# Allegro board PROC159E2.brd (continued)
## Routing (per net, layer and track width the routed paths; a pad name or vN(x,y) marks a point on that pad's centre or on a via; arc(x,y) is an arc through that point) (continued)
HSEC_EPWM1_A: length 63.2
  TOP w0.147: J15.53 v1(38.24,4.56) ; U1.D3 v1(54.58,44.83)
  L03_SIG1 w0.091: v1(54.58,44.83) 54.97,45.22 54.97,45.79 54.74,46.02 54.44,46.02 54.17,46.29 54.17,47.39 53.74,47.82 51.8,47.82 49.82,45.83 49.82,38.37 49.3,37.86 49.3,33.4 46.26,30.36 46.26,29.3 43.51,26.55 42.45,26.55 37.56,21.65 37.56,18.1 35.67,16.21 35.67,6.48 34.75,5.56 34.75,4.73 35.35,4.13 37.81,4.13 v1(38.24,4.56)
HSEC_EPWM1_B: length 50.9
  TOP w0.147: U1.D2 v1(53.78,44.83) ; J15.55 39.04,3.61 38.73,3.92 38.73,6.1 v1(38.24,6.59)
  L03_SIG1 w0.091: v1(38.24,6.59) 38.24,6.96 38.4,7.13 38.4,12.85 38.76,13.21 38.76,20.25 47.37,28.86 47.37,29.84 50.4,32.87 50.4,37 51.11,37.71 51.11,43.51 52.82,45.22 53.39,45.22 v1(53.78,44.83)
HSEC_EPWM2_A: length 52.7
  TOP w0.147: U1.C2 v1(53.78,45.63)
  L03_SIG1 w0.091: v1(36.64,5.58) 36.64,5.95 37.88,7.19 37.88,10.06 37.58,10.36 37.58,17.09 38.37,17.88 38.37,20.37 46.99,29 46.99,30 50.04,33.04 50.04,37.29 50.69,37.93 50.69,44 52.71,46.02 53.16,46.02 53.55,45.63 v1(53.78,45.63)
  BOTTOM w0.147: v1(36.64,5.58) 37.09,5.12 37.09,4.37 36.64,3.92 J15.50
HSEC_EPWM2_B: length 50.5
  TOP w0.147: U1.C1 v1(52.98,45.63)
  L03_SIG1 w0.091: v1(37.44,5.58) 37.44,6.44 38.15,7.15 38.15,13.16 38.56,13.58 38.56,20.31 47.19,28.94 47.19,29.92 50.22,32.95 50.22,37.15 50.89,37.82 50.89,43.92 52.61,45.63 v1(52.98,45.63)
  BOTTOM w0.147: J15.52 v1(37.44,5.58)
HSEC_EPWM3_A: length 43.1
  TOP w0.147: U1.E2 v1(53.78,44.03) ; U73.11 48.52,13.64 v1(49.64,14.75)
  L03_SIG1 w0.091: v1(49.64,14.75) 53.49,18.61 55.15,18.61 55.72,19.17 55.72,20.44 55.3,20.86 55.3,29.64 58.17,32.51 58.17,39.6 57.78,39.99 56.97,39.99 56.57,40.4 56.57,44.19 56.34,44.42 55.22,44.42 54.97,44.17 54.97,43.87 54.74,43.64 54.17,43.64 v1(53.78,44.03)
HSEC_EPWM3_A/HSEC_MII1_CRS(RES0: length 33
  TOP w0.147: U73.9 v1(47.22,13.18)
  BOTTOM w0.147: C318.1 31.98,11.19 U68.3 ; C318.1 31.98,8.26 33.2,7.05 36.83,7.05 38.69,5.18 38.69,4.07 38.24,3.61 J15.54 ; C318.1 34.59,9.89 35.81,8.68 42.72,8.68 v1(47.22,13.18)
HSEC_EPWM3_B: length 58.1
  TOP w0.147: U1.E3 v1(54.58,44.03)
  L03_SIG1 w0.091: v1(54.58,44.03) 54.19,44.42 54.19,45.77 53.92,46.04 53.62,46.04 53.37,46.29 53.37,46.59 53.14,46.82 52.71,46.82 50.24,44.35 50.24,38.13 49.67,37.56 49.67,33.2 46.63,30.15 46.63,29.15 37.98,20.5 37.98,18 36.04,16.06 36.04,8.4 v1(36.7,7.73)
  BOTTOM w0.147: v1(36.7,7.73) 38.35,7.73 39.04,7.04 J15.56
HSEC_EPWM4_A: length 51.2
  TOP w0.147: v1(43.84,6.59) 43.04,5.79 J15.57 ; U1.D1 v1(52.98,44.83)
  L03_SIG1 w0.091: v1(43.84,6.59) 38.95,11.48 38.95,20.18 47.56,28.79 47.56,29.77 50.59,32.8 50.59,36.88 51.33,37.62 51.33,43.18 v1(52.98,44.83)
HSEC_EPWM4_B: length 56.3
  TOP w0.147: U1.E4 v1(55.38,44.03) ; J15.59 v1(43.84,4.56)
  L03_SIG1 w0.091: v1(55.38,44.03) 55.38,44 54.97,43.58 54.97,40.47 54.68,40.18 53.69,40.18 53.34,39.83 53.34,36.61 52.97,36.25 52.97,35.3 52.48,34.81 52.48,33.03 49.41,29.96 49.41,29.09 42.85,22.53 42.85,18.97 40.36,16.48 40.36,12.7 44.42,8.64 44.77,8.64 46.42,6.99 46.42,5.59 47.02,4.99 47.22,4.99 47.47,4.74 47.47,4.38 47.22,4.13 44.27,4.13 v1(43.84,4.56)
HSEC_EPWM5_A: length 51.6
  TOP w0.147: U1.F2 v1(53.78,43.23) ; J15.61 44.64,5.79 v1(45.44,6.59)
  L03_SIG1 w0.091: v1(53.78,43.23) 53.39,43.62 52.71,43.62 51.75,42.66 51.75,36.48 51.52,36.25 51.52,35.6 51.69,35.42 51.69,33.36 48.68,30.34 48.68,29.4 39.31,20.02 39.31,12.72 v1(45.44,6.59)
HSEC_EPWM5_B: length 49.6
  TOP w0.147: U1.G2 v1(53.78,42.43) ; J15.63 v1(45.44,4.56)
  L03_SIG1 w0.091: v1(53.78,42.43) 53.52,42.17 53.48,42.17 52.42,41.1 52.42,36.94 52.77,36.59 52.77,35.42 52.27,34.92 52.27,33.11 49.23,30.08 49.23,29.17 42.44,22.37 42.44,18.94 40.12,16.62 40.12,12.69 44.35,8.46 44.69,8.46 46.23,6.92 46.23,5.35 v1(45.44,4.56)
HSEC_EPWM6_A: length 51
  TOP w0.147: U1.E1 v1(52.98,44.03)
  L03_SIG1 w0.091: v1(52.98,44.03) 52.61,44.03 51.54,42.96 51.54,37.53 50.77,36.76 50.77,34.79 51.47,34.09 51.47,33.41 47.74,29.69 47.74,28.71 39.13,20.1 39.13,12.27 v1(43.84,7.56)
  BOTTOM w0.147: v1(43.84,7.56) 43.52,7.24 43.47,7.24 43.04,6.81 J15.58
HSEC_EPWM6_B: length 54.4
  TOP w0.147: U1.F3 v1(54.58,43.23)
  L03_SIG1 w0.091: v1(54.58,43.23) 54.17,42.82 52.82,42.82 52.19,42.19 52.19,36.81 52.57,36.43 52.57,35.51 52.08,35.03 52.08,33.23 49.05,30.19 49.05,29.24 39.68,19.87 39.68,12.87 44.27,8.28 44.61,8.28 46.05,6.84 46.05,5.58 45.62,5.15 44.27,5.15 v1(43.84,5.58)
  BOTTOM w0.147: v1(43.84,5.58) 43.38,5.12 43.38,4.37 43.84,3.92 J15.60
HSEC_EPWM7_A: length 51.4
  TOP w0.147: U1.F4 v1(55.38,43.23)
  L03_SIG1 w0.091: v1(45.59,8.83) 44.5,8.83 40.63,12.69 40.63,16.43 46.47,22.27 46.47,25.89 49.6,29.02 49.6,29.85 52.69,32.94 52.69,34.71 53.19,35.21 53.19,36.18 54.17,37.16 54.17,39.62 54.41,39.87 55.26,39.87 55.77,40.38 55.77,42.84 v1(55.38,43.23)
  BOTTOM w0.147: v1(45.59,8.83) 45.59,7.76 44.64,6.81 J15.62
HSEC_EPWM7_B: length 50.7
  TOP w0.147: U1.F1 v1(52.98,43.23)
  L03_SIG1 w0.091: v1(52.98,43.23) 52.61,43.23 51.96,42.59 51.96,36.43 51.7,36.17 51.7,35.71 51.88,35.54 51.88,33.28 48.86,30.27 48.86,29.32 39.49,19.95 39.49,12.8 45.18,7.11 45.52,7.11 45.87,6.77 45.87,6 v1(45.44,5.58)
  BOTTOM w0.147: v1(45.44,5.58) 44.98,5.12 44.98,4.37 45.44,3.92 J15.64
HSEC_EPWM11_A: length 67.9
  TOP w0.147: v1(47.62,45.45) 48.13,44.95 49.04,44.95 R190.2
  L03_SIG1 w0.091: v1(47.62,45.45) 48,45.07 48.5,45.07 49.59,43.98 49.59,38.54 49.12,38.06 49.12,34.5 37.08,22.46 v1(37.08,20.43)
  BOTTOM w0.147: v1(37.08,20.43) 48.55,20.43 51.54,17.45 53.42,17.45 54.36,16.51 54.36,15.84 55.68,14.52 55.68,12.42 56.35,11.75 56.35,8.73 54.24,6.62 J15.86
HSEC_EPWM13_A: length 108.5
  TOP w0.147: v1(102.44,5.58) 102.44,4.87 101.64,4.07 J15.153
  L08_SIG2 w0.091: v1(102.44,5.58) 101.67,5.58 101.18,6.07 99.06,6.07 98.01,7.11 97.42,7.11 97.03,7.51 97.03,8.69 90.94,14.77 87.73,14.77 82.67,19.83 82.67,27.73 79,31.4 79,38.58 77.39,40.19 77.39,45.49 75.06,47.82 75.06,48.91 73.62,50.35 70.8,50.35 70.48,50.67 70.48,51.2 69.55,52.13 67.79,52.13 67.03,52.89 66.03,52.89 64.87,54.06 58.3,54.06 55.76,51.51 45.03,51.51 44.23,50.72 44.23,48.09 45.11,47.22 48.66,47.22 49.4,46.48 49.4,45.24 v1(48.51,44.35)
  BOTTOM w0.147: R192.2 v1(48.51,44.35)
HSEC_EPWM13_B: length 112
  L08_SIG2 w0.091: v1(48.51,43.21) 48.08,43.64 48.08,44.53 48.33,44.78 48.66,44.78 49.12,45.24 49.12,46.32 48.56,46.88 45.07,46.88 43.97,47.98 43.97,50.78 44.88,51.69 55.56,51.69 58.12,54.25 64.95,54.25 66.11,53.09 67.11,53.09 67.87,52.33 69.7,52.33 70.75,51.27 70.75,50.79 70.94,50.6 73.78,50.6 75.17,49.22 76.83,49.22 77.66,48.38 77.66,40.31 79.24,38.73 79.24,31.5 82.91,27.83 82.91,20.02 87.87,15.06 92.18,15.06 98.36,8.88 98.36,7.71 98.97,7.1 101.07,7.1 101.58,6.59 v1(102.44,6.59)
  BOTTOM w0.147: J15.154 101.64,4.06 101.91,4.34 101.91,6.07 v1(102.44,6.59) ; R196.2 v1(48.51,43.21)
HSEC_EPWM21_A: length 45.1
  TOP w0.147: J15.89 55.84,5.87 v1(55.09,6.61) ; v1(74.47,35.69) 74.21,35.95 R209.2
  L03_SIG1 w0.091: v1(55.09,6.61) 55.52,6.61 63.52,14.61 65.34,14.61 69.32,18.59 69.32,22.46 70.98,24.13 70.98,26.99 73.72,29.74 73.72,30.96 75.94,33.18 75.94,34.22 v1(74.47,35.69)
HSEC_EPWM21_B: length 47.1
  TOP w0.147: R207.2 74.21,38.51 74.47,38.26 v1(74.47,37.75)
  L03_SIG1 w0.091: v1(56.6,6.61) 56.6,7.14 63.74,14.28 65.49,14.28 69.61,18.4 69.61,22.38 71.22,23.99 71.22,26.78 74.08,29.64 74.08,30.47 76.29,32.67 76.29,35.93 v1(74.47,37.75)
  BOTTOM w0.147: v1(56.6,6.61) 55.84,5.85 J15.90
HSEC_EQEP0_A: length 59
  TOP w0.147: U1.B14 v1(64.18,46.43)
  L08_SIG2 w0.091: v1(64.18,46.43) 64.59,46.84 65.14,46.84 65.37,47.07 65.37,47.37 65.62,47.62 66.23,47.62 66.94,46.91 66.94,45.43 71.39,40.97 71.39,39.4 72.03,38.75 72.03,34.76 70.41,33.14 70.41,30.21 71.59,29.03 71.59,27.48 71.17,27.06 71.17,23.86 69.8,22.49 69.8,18.7 66.92,15.82 65.18,15.82 60.04,10.67 60.04,8.41 60.83,7.62 61.17,7.62 v1(61.43,7.35)
  BOTTOM w0.147: J15.102 60.64,6.56 v1(61.43,7.35)
HSEC_EQEP0_B: length 67.7
  TOP w0.147: U1.A14 v1(64.18,47.23)
  L08_SIG2 w0.091: v1(64.18,47.23) 65.01,48.06 67.48,48.06 68.36,47.19 68.36,44.99 69.71,43.63 70.45,43.63 71.06,43.02 71.06,42.06 72.7,40.41 72.7,34.66 72.22,34.17 72.22,27.03 73.67,25.57 73.67,23.68 72.49,22.5 72.49,18.69 71.67,17.87 69.51,17.87 64.94,13.3 64.94,10.54 64.33,9.93 62.85,9.93 61.51,11.26 61.01,11.26 60.22,10.47 60.22,8.49 60.81,7.9 61.49,7.9 61.87,7.52 61.87,6.41 61.62,6.16 60.11,6.16 v1(59.81,6.46)
  BOTTOM w0.147: v1(59.81,6.46) 60.29,5.98 60.29,4.37 59.84,3.91 J15.100
HSEC_EQEP0_INDEX: length 76.8
  TOP w0.147: U1.D11 v1(61.78,44.83)
  L08_SIG2 w0.091: v1(61.78,44.83) 62.17,45.22 62.17,52.26 62.76,52.84 63.48,52.84 63.86,52.47 63.86,51.78 65.44,50.2 66.74,50.2 67.46,49.48 68.19,49.48 69.87,47.8 70.51,47.8 70.89,47.42 70.89,46.17 73.38,43.69 74.14,43.69 74.49,43.34 74.49,38.83 75.17,38.15 75.17,34.83 76.16,33.84 76.16,17.77 75.13,16.75 69.97,16.75 67.34,14.12 67.34,13.27 66.56,12.49 66.56,10.15 63.99,7.57 v1(63.03,7.57)
  BOTTOM w0.147: J15.106 62.24,6.78 v1(63.03,7.57)
HSEC_EQEP0_STROBE: length 69.7
  TOP w0.147: U1.C12 v1(62.58,45.63)
  L08_SIG2 w0.091: v1(62.58,45.63) 62.99,46.04 62.99,46.59 63.37,46.97 63.37,47.85 64.82,49.3 66.39,49.3 67.09,48.61 67.65,48.61 68.85,47.41 68.85,45.19 69.92,44.12 70.99,44.12 73.43,41.68 73.43,34.62 72.88,34.06 72.88,31.42 73.43,30.87 73.43,29.58 72.96,29.11 72.96,26.97 74.16,25.78 74.16,23.48 72.98,22.3 72.98,18.49 71.99,17.5 69.66,17.5 65.31,13.15 65.31,10.39 64.41,9.49 60.96,9.49 60.6,9.13 60.6,8.62 60.96,8.27 61.64,8.27 62.23,7.68 62.23,5.92 61.81,5.5 v1(61.44,5.5)
  BOTTOM w0.147: J15.104 61.44,3.92 60.98,4.37 60.98,5.04 v1(61.44,5.5)
HSEC_EQEP2_A: length 137
  L08_SIG2 w0.091: v1(24.82,18.59) 24.23,18.59 24.04,18.41 18.48,18.41 13.71,23.18 13.71,26.78 12.81,27.68 12.81,31.58 13.49,32.25 14.05,32.25 17.03,35.23 17.03,36.69 14.76,38.96 14.76,53.8 19.09,58.13 19.09,60.71 26.15,67.77 28,67.77 29.01,68.78 v1(46.04,68.78)
  BOTTOM w0.147: U26.6 46.22,68.96 v1(46.04,68.78) ; v1(24.82,18.59) 26.14,19.92 35.77,19.92 37.09,21.24 49.31,21.24 52.58,17.98 55.17,17.98 57.14,16 57.14,4.42 56.83,4.1 56.82,4.1 56.64,3.93 J15.92
HSEC_EQEP2_B: length 148.8
  TOP w0.147: J15.93 57.44,5.79 v1(58.24,6.59)
  L08_SIG2 w0.091: v1(23.87,17.51) 17.46,17.51 12.96,22.01 12.96,22.81 11.79,23.98 11.08,23.98 10.09,24.97 10.09,31.65 11.24,32.8 13.83,32.8 15.54,34.52 15.54,36.88 13.9,38.53 13.9,58.78 26.2,71.08 30.54,71.08 31.32,70.29 45.6,70.29 v1(46.03,70.73)
  BOTTOM w0.147: v1(46.03,70.73) 46.05,70.73 46.23,70.91 U26.3 ; v1(58.24,6.59) 58.24,7.15 59.77,8.68 59.77,14.55 56.05,18.27 52.7,18.27 49.43,21.54 36.97,21.54 35.64,20.21 25.81,20.21 24.65,19.05 24.63,19.05 23.87,18.29 v1(23.87,17.51)
HSEC_EQEP2_INDEX: length 71.5
  TOP w0.147: U1.A12 v1(62.58,47.23)
  L08_SIG2 w0.091: v1(62.58,47.23) 62.58,48.05 64.32,49.79 66.57,49.79 67.3,49.05 67.89,49.05 69.33,47.61 69.33,46.42 73.92,41.83 73.92,34.48 74.25,34.15 74.39,34.15 74.89,33.66 74.89,31.49 74.56,31.16 74.56,28.83 75.54,27.85 75.54,17.84 74.83,17.14 69.81,17.14 65.82,13.15 65.82,11.26 66.38,10.7 66.38,10.22 65.03,8.88 v1(61.21,8.88)
  BOTTOM w0.147: v1(61.21,8.88) 60.38,8.88 58.69,7.19 58.69,6.4 57.44,5.15 J15.94
HSEC_EQEP2_STROBE: length 77.2
  TOP w0.147: J15.95 v1(58.24,4.56) ; U1.B12 v1(62.58,46.43)
  L08_SIG2 w0.091: v1(58.24,4.56) 58.67,4.99 60.02,4.99 60.27,4.74 60.27,4.61 61.11,3.77 62.85,3.77 63.47,4.38 63.47,6.67 63.17,6.96 62.78,6.96 62.42,7.32 62.42,7.74 61.71,8.45 61.03,8.45 60.78,8.7 60.78,9.05 61.03,9.3 64.48,9.3 65.49,10.31 65.49,13.07 69.74,17.32 74.67,17.32 75.3,17.94 75.3,27.75 73.91,29.14 73.91,33.88 73.68,34.11 73.68,41.75 71.09,44.34 70.01,44.34 69.07,45.28 69.07,47.53 67.78,48.83 67.19,48.83 66.47,49.54 64.61,49.54 63.08,48.01 63.08,47.16 62.58,46.66 v1(62.58,46.43)
HSEC_EXT_REFCLK0: length 45.5
  TOP w0.147: U1.P2 v1(53.78,36.03)
  L03_SIG1 w0.091: v1(53.78,36.03) 53.39,35.64 53.39,35.08 52.91,34.6 52.91,32.85 49.78,29.73 49.78,28.94 47.94,27.1 47.94,22.72 41.38,16.16 41.38,12.72 44.43,9.67 46.2,9.67 47.26,8.62 49.23,8.62 v1(50.24,7.61)
  BOTTOM w0.147: J15.74 49.44,6.81 v1(50.24,7.61)
HSEC_GPIO: length 94.1
  TOP w0.147: v1(52.75,67.83) 52.25,68.33 45.59,68.33 44.37,67.11 44.37,61.86 43.83,61.31 43.83,60.4 46.44,57.78 v1(46.44,56.66)
  BOTTOM w0.147: v1(46.44,56.66) 46.44,55.92 42.39,51.87 42.39,47.14 47.05,42.48 47.05,40.79 45.35,39.09 45.35,36.74 43.95,35.35 43.95,31.83 49.1,26.69 49.1,24.3 51.47,21.92 57.47,21.92 58.58,20.81 58.58,17.73 61.72,14.6 61.72,8.74 60.02,7.05 59.75,7.05 58.99,6.28 58.99,6.28 57.78,5.08 57.78,4.37 58.24,3.92 J15.96 ; U60.17 52.9,68.24 52.75,68.09 v1(52.75,67.83)
HSEC_I2C1_SCL: length 97.8
  TOP w0.147: U1.D7 v1(57.78,44.83) ; J15.87 v1(55.04,4.56) ; R152.2 v1(57.84,49.14)
  L08_SIG2 w0.091: v1(55.04,4.56) 56.2,3.4 63,3.4 63.83,4.23 63.83,6.64 66.79,9.6 67.11,9.92 67.11,12.21 69.29,14.39 74.72,14.39 81.14,20.81 81.14,28.6 78.45,31.28 78.45,38.35 76.84,39.97 76.84,43.97 74.47,46.33 74.47,48.69 73.33,49.82 70.06,49.82 69.26,50.62 69.26,51.24 68.75,51.75 67.62,51.75 66.86,52.51 65.87,52.51 64.79,53.58 61.72,53.58 60.45,52.32 60.11,52.32 59.53,51.74 59.53,51.4 57.84,49.71 v1(57.84,49.14) 59.17,47.8 59.17,46.77 58.97,46.57 58.97,45.47 58.74,45.24 58.19,45.24 v1(57.78,44.83)
HSEC_I2C1_SDA: length 103
  TOP w0.147: v1(55.03,5.62) 54.71,5.3 54.71,5.29 54.24,4.82 J15.85 ; R153.2 v1(56.7,49.14) ; U1.C8 v1(58.58,45.63)
  L08_SIG2 w0.091: v1(55.03,5.62) 54.61,5.21 54.61,4.38 55.78,3.22 63.08,3.22 64.01,4.16 64.01,6.45 67.3,9.74 67.3,12.14 69.37,14.21 74.88,14.21 81.38,20.71 81.38,28.67 78.76,31.3 78.76,38.44 77.11,40.08 77.11,45.38 74.83,47.66 74.83,48.74 73.46,50.1 70.18,50.1 69.51,50.76 69.51,51.4 68.97,51.94 67.7,51.94 66.94,52.7 65.95,52.7 64.87,53.79 61.5,53.79 60.36,52.64 59.98,52.64 59.52,52.18 58.56,52.18 56.7,50.32 v1(56.7,49.14) 57.18,48.65 57.8,48.65 58.97,47.48 58.97,47.07 58.74,46.84 58.44,46.84 58.19,46.59 58.19,46.02 v1(58.58,45.63)
HSEC_MCAN5_RX: length 48.3
  L03_SIG1 w0.091: v1(47.38,24.5) 46.9,24.02 46.9,22.37 40.9,16.37 40.9,12.68 44.28,9.31 45.97,9.31 47.03,8.25 48.6,8.25 49.81,7.04 49.81,6.41 50.65,5.58 v1(51.84,5.58)
  BOTTOM w0.147: v1(51.84,5.58) 51.38,5.12 51.38,4.37 51.84,3.92 J15.80 ; v1(47.38,24.5) 45.86,26.01 43.96,26.01 38.15,31.82 U33.11
HSEC_MCAN5_TX: length 50
  L03_SIG1 w0.091: v1(53.44,7.61) 53.01,7.18 50.06,7.18 48.81,8.43 47.11,8.43 46.05,9.49 44.35,9.49 41.16,12.68 41.16,16.29 47.33,22.46 v1(47.33,23.63)
  BOTTOM w0.147: U33.14 35.34,29.87 36.3,30.83 38.64,30.83 43.8,25.67 45.28,25.67 v1(47.33,23.63) ; J15.82 52.64,6.81 v1(53.44,7.61)
HSEC_MII0_COL: length 122.7
  TOP w0.147: v1(72.9,66.32) 73.3,65.92 73.3,64.07 73.98,63.39 U87.24
  L03_SIG1 w0.091: v1(72.9,66.32) 73.19,66.02 75.49,66.02 76.96,67.49 76.96,67.78 77.37,68.19 78.64,68.19 84.17,62.66 84.17,56.59 86.42,54.34 86.42,49.64 86.81,49.25 86.81,47.35 86.5,47.04 86.5,44.42 83.8,41.72 83.8,32.88 84.78,31.9 84.78,22.98 89.31,18.45 89.31,17.23 90.24,16.3 90.65,16.3 90.96,15.99 90.96,15.38 91.61,14.73 91.61,13.7 92.27,13.05 92.27,12.33 91.65,11.71 91.65,8.88 92.13,8.39 92.62,8.39 93.1,8.86 v1(93.51,8.86)
  BOTTOM w0.147: v1(93.51,8.86) 93.89,9.25 93.89,10.64 93.07,11.46 90.43,11.46 89.62,12.27 89.62,12.74 88.76,13.6 69.83,13.6 69.23,12.99 69.23,11.79 64.64,7.2 64.64,6.59 63.62,5.57 63.62,4.26 63.84,4.04 J15.110
HSEC_MII0_CRS: length 87.8
  TOP w0.147: v1(92.46,8.87) 90,8.87 88.84,7.71 J15.121 ; U87.22 74.17,65 v1(74.17,66.7)
  L03_SIG1 w0.091: v1(92.46,8.87) 92.08,8.87 91.89,9.06 91.89,11.55 92.54,12.2 92.54,13.16 91.93,13.78 91.93,14.81 91.24,15.5 91.24,16.19 90.95,16.48 90.95,16.96 90.65,17.26 90.19,17.26 89.69,17.76 89.69,18.58 85.05,23.22 85.05,32.02 84.07,33 84.07,41.6 86.78,44.31 86.78,45.98 87.85,47.05 87.85,48.64 86.69,49.8 86.69,54.46 84.44,56.71 84.44,62.78 83.52,63.69 79.08,68.13 79.08,68.79 78.76,69.11 77.37,69.11 76.55,68.29 76.55,67.94 75.82,67.21 74.68,67.21 v1(74.17,66.7)
HSEC_MII0_RXCLK: length 98.1
  TOP w0.147: J15.123 89.64,3.85 90.15,4.36 90.15,7.16 v1(89.57,7.73) ; U87.28 v1(73.94,61.39)
  L03_SIG1 w0.091: v1(73.94,61.39) 73.48,61.85 73.48,62.56 75.2,64.28 77.86,64.28 78.69,65.11 79.32,65.11 82,62.43 82,61.39 81.76,61.16 81.76,51.26 80.68,50.17 80.68,44.55 81.09,44.13 81.09,42.48 79.46,40.85 79.46,28.97 79.82,28.61 79.82,27.82 80.29,27.35 80.29,26.76 80.42,26.62 80.78,26.62 80.91,26.49 80.91,26.3 80.78,26.17 80.42,26.17 80.29,26.03 80.29,25.84 80.42,25.71 80.78,25.71 80.91,25.57 80.91,25.39 80.78,25.25 80.42,25.25 80.29,25.12 80.29,24.93 80.42,24.79 80.78,24.79 80.91,24.66 80.91,24.47 80.78,24.34 80.42,24.34 80.29,24.2 80.29,24.01 80.42,23.88 80.78,23.88 80.91,23.75 80.91,23.56 80.78,23.42 80.42,23.42 80.29,23.29 80.29,23.1 80.42,22.97 80.78,22.97 80.91,22.83 80.91,22.64 80.78,22.51 80.42,22.51 80.29,22.37 80.29,22.19 80.42,22.05 80.78,22.05 80.91,21.92 80.91,21.73 80.78,21.59 80.42,21.59 80.29,21.46 80.29,21.27 80.42,21.14 80.78,21.14 80.91,21 80.91,20.81 80.78,20.68 80.42,20.68 80.29,20.55 80.29,19.55 78.25,17.52 78.25,16.45 78.64,16.06 79.39,16.06 79.52,16.2 79.52,16.6 79.65,16.74 79.84,16.74 79.98,16.6 79.98,16.2 80.11,16.06 80.3,16.06 80.43,16.2 80.43,16.6 80.57,16.74 80.76,16.74 80.89,16.6 80.89,16.2 81.03,16.06 81.22,16.06 81.35,16.2 81.35,16.6 81.48,16.74 81.67,16.74 81.81,16.6 81.81,16.2 81.94,16.06 82.13,16.06 82.26,16.2 82.26,16.6 82.4,16.74 82.59,16.74 82.72,16.6 82.72,16.2 82.85,16.06 83.04,16.06 83.18,16.2 83.18,16.6 83.31,16.74 83.5,16.74 83.63,16.6 83.63,16.2 83.77,16.06 83.96,16.06 84.09,16.2 84.09,16.6 84.23,16.74 84.42,16.74 84.55,16.6 84.55,16.2 84.68,16.06 86.66,16.06 89.27,13.46 89.27,8.04 v1(89.57,7.73)
HSEC_MII0_RXD0: length 98.3
  TOP w0.147: v1(72.18,55.11) 72.93,54.36 76.63,54.36 77.22,54.95 U87.42 ; J15.125 90.44,4.1 90.73,4.4 90.73,7.1 v1(91.24,7.61)
  L03_SIG1 w0.091: v1(91.24,7.61) 91.24,11.69 91.99,12.44 91.99,12.9 91.34,13.55 91.34,14.58 90.68,15.23 90.41,15.23 88.74,16.89 88.74,18.46 84.5,22.7 84.5,31.75 83.52,32.73 83.52,41.84 85.09,43.4 85.09,48.92 84.65,49.36 84.65,53.58 83.89,54.34 83.89,62.48 79.17,67.2 77.15,67.2 75.65,65.69 72.69,65.69 70.55,63.55 70.55,58.42 71.01,57.97 71.4,57.97 71.72,57.64 71.72,56.64 72.18,56.17 v1(72.18,55.11)
HSEC_MII0_RXD1: length 98.2
  TOP w0.147: U87.40 76.22,55.26 76.07,55.11 74.99,55.11 74.79,55.32 v1(74.33,55.32)
  L03_SIG1 w0.091: v1(74.33,55.32) 74.61,55.59 74.61,59 74.2,59.41 73.74,59.41 73.5,59.65 73.5,61.45 73.21,61.73 73.21,62.75 75.02,64.56 77.75,64.56 78.57,65.38 79.44,65.38 82.33,62.48 82.33,61.3 82.04,61 82.04,51.15 80.95,50.06 80.95,44.66 81.37,44.25 81.37,42.3 79.73,40.67 79.73,29.87 81.42,28.19 81.42,24.54 81.55,24.41 81.95,24.41 82.08,24.27 82.08,24.08 81.95,23.95 81.55,23.95 81.42,23.81 81.42,23.63 81.55,23.49 81.95,23.49 82.08,23.36 82.08,23.17 81.95,23.03 81.55,23.03 81.42,22.9 81.42,22.71 81.55,22.58 81.95,22.58 82.08,22.44 82.08,22.25 81.95,22.12 81.55,22.12 81.42,21.99 81.42,21.8 81.55,21.66 81.95,21.66 82.08,21.53 82.08,21.34 81.95,21.21 81.55,21.21 81.42,21.07 81.42,20.88 81.55,20.75 81.95,20.75 82.08,20.61 82.08,20.43 81.95,20.29 81.55,20.29 81.42,20.16 81.42,19.97 81.55,19.83 81.95,19.83 82.08,19.7 82.08,19.51 81.95,19.38 81.55,19.38 81.42,19.24 81.42,19.05 81.55,18.92 81.95,18.92 82.08,18.79 82.08,18.6 81.95,18.46 81.55,18.46 81.42,18.33 81.42,17.79 81.97,17.24 85.87,17.24 89.54,13.57 89.54,9.65 90.01,9.19 90.01,5.94 v1(89.64,5.58)
  BOTTOM w0.147: J15.126 90.44,4.78 v1(89.64,5.58)
HSEC_MII0_RXD2: length 98.6
  TOP w0.147: U87.37 v1(73.94,56.89) ; J15.127 91.24,3.9 91.71,4.37 91.71,5.1 v1(91.24,5.58)
  L03_SIG1 w0.091: v1(73.94,56.89) 72.43,58.4 71.86,58.4 71.37,58.89 70.99,58.89 70.83,59.06 70.83,63.44 72.81,65.42 77.45,65.42 78.23,66.2 79.78,66.2 83.32,62.66 83.32,61.13 82.86,60.66 82.86,50.24 83.76,49.34 83.76,47.07 82.53,45.84 82.53,36.36 82.66,36.23 82.98,36.23 83.11,36.09 83.11,35.9 82.98,35.77 82.66,35.77 82.53,35.64 82.53,35.45 82.66,35.31 82.98,35.31 83.11,35.18 83.11,34.99 82.98,34.86 82.66,34.86 82.53,34.72 82.53,34.53 82.66,34.4 82.98,34.4 83.11,34.26 83.11,34.07 82.98,33.94 82.66,33.94 82.53,33.81 82.53,33.62 82.66,33.48 82.98,33.48 83.11,33.35 83.11,33.16 82.98,33.03 82.66,33.03 82.53,32.89 82.53,32.7 82.66,32.57 82.98,32.57 83.11,32.44 83.11,32.25 82.98,32.11 82.66,32.11 82.53,31.98 82.53,31.79 82.66,31.65 82.98,31.65 83.11,31.52 83.11,31.33 82.98,31.2 82.66,31.2 82.53,31.06 82.53,30.87 82.66,30.74 82.98,30.74 83.11,30.61 83.11,30.42 82.98,30.28 82.66,30.28 82.53,30.15 82.53,29.96 82.66,29.83 82.98,29.83 83.11,29.69 83.11,29.5 82.98,29.37 82.66,29.37 82.53,29.23 82.53,28.82 83.33,28.01 83.33,19.06 83.88,18.51 85.93,18.51 89.5,14.94 90.58,14.94 91.03,14.49 91.03,13.38 91.14,13.28 91.14,12.33 90.8,12 90.8,6.01 v1(91.24,5.58)
HSEC_MII0_RXD3: length 98.4
  TOP w0.147: U87.35 v1(73.94,57.89)
  L03_SIG1 w0.091: v1(73.94,57.89) 73.41,57.89 72.86,58.44 72.86,58.87 72.34,59.39 71.99,59.39 71.68,59.7 71.68,63.11 71.96,63.39 72.98,63.39 74.73,65.15 77.56,65.15 78.34,65.93 79.66,65.93 82.97,62.62 82.97,61.16 82.59,60.78 82.59,49.88 82.86,49.6 82.86,46.57 82.17,45.88 82.17,41.1 82.04,40.97 81.29,40.97 81.16,40.83 81.16,40.65 81.29,40.51 82.04,40.51 82.17,40.38 82.17,39.55 81.54,38.91 81.54,38.59 81.67,38.46 81.99,38.46 82.13,38.32 82.13,38.13 81.99,38 81.67,38 81.54,37.87 81.54,37.68 81.67,37.54 81.99,37.54 82.13,37.41 82.13,37.22 81.99,37.09 81.67,37.09 81.54,36.95 81.54,36.76 81.67,36.63 81.99,36.63 82.13,36.49 82.13,36.3 81.99,36.17 81.67,36.17 81.54,36.04 81.54,35.85 81.67,35.71 81.99,35.71 82.13,35.58 82.13,35.39 81.99,35.26 81.67,35.26 81.54,35.12 81.54,34.93 81.67,34.8 81.99,34.8 82.13,34.67 82.13,34.48 81.99,34.34 81.67,34.34 81.54,34.21 81.54,34.02 81.67,33.88 81.99,33.88 82.13,33.75 82.13,33.56 81.99,33.43 81.67,33.43 81.54,33.29 81.54,33.1 81.67,32.97 81.99,32.97 82.13,32.84 82.13,32.65 81.99,32.51 81.67,32.51 81.54,32.38 81.54,32.19 81.67,32.06 81.99,32.06 82.13,31.92 82.13,31.73 81.99,31.6 81.67,31.6 81.54,31.46 81.54,31.28 81.67,31.14 81.99,31.14 82.13,31.01 82.13,30.82 81.99,30.68 81.67,30.68 81.54,30.55 81.54,30.36 81.67,30.23 81.99,30.23 82.13,30.09 82.13,29.9 81.99,29.77 81.67,29.77 81.54,29.64 81.54,29.25 82.98,27.81 82.98,18.63 83.46,18.15 85.81,18.15 90.86,13.1 90.86,12.44 90.55,12.13 90.55,5.25 v1(91.24,4.56)
  BOTTOM w0.147: J15.128 v1(91.24,4.56)
HSEC_MII0_RXDV: length 98.3
  TOP w0.147: U87.33 v1(73.94,58.89)
  L03_SIG1 w0.091: v1(89.64,4.56) 90.26,5.19 90.26,9.36 89.81,9.81 89.81,13.71 85.84,17.69 83.14,17.69 82.59,18.24 82.59,24.71 82.45,24.85 81.91,24.85 81.78,24.98 81.78,25.17 81.91,25.3 82.45,25.3 82.59,25.44 82.59,25.63 82.45,25.76 81.91,25.76 81.78,25.89 81.78,26.08 81.91,26.22 82.45,26.22 82.59,26.35 82.59,27.76 80.76,29.59 80.76,32.25 80.01,33 80.01,34.27 80.14,34.41 81.05,34.41 81.19,34.54 81.19,34.73 81.05,34.86 80.14,34.86 80.01,35 80.01,35.19 80.14,35.32 81.05,35.32 81.19,35.46 81.19,35.64 81.05,35.78 80.14,35.78 80.01,35.91 80.01,36.87 80.14,37.01 81.07,37.01 81.21,37.14 81.21,37.33 81.07,37.46 80.14,37.46 80.01,37.6 80.01,37.79 80.14,37.92 81.07,37.92 81.21,38.05 81.21,38.24 81.07,38.38 80.14,38.38 80.01,38.51 80.01,38.7 80.14,38.83 81.07,38.83 81.21,38.97 81.21,39.16 81.07,39.29 80.14,39.29 80.01,39.43 80.01,40.36 81.64,41.99 81.64,46.54 81.98,46.88 81.98,50.67 82.31,51 82.31,60.89 82.64,61.22 82.64,62.57 79.55,65.66 78.46,65.66 77.67,64.87 74.84,64.87 72.87,62.9 72.87,60.38 72.59,60.1 72.59,59.66 73.36,58.89 v1(73.94,58.89)
  BOTTOM w0.147: J15.124 v1(89.64,4.56)
HSEC_MII0_RXER: length 98.2
  TOP w0.147: U87.31 v1(73.94,59.89)
  L03_SIG1 w0.091: v1(73.94,59.89) 73.94,60.5 74.61,61.18 74.61,62.28 75.45,63.12 77.69,63.12 78.5,63.93 79.72,63.93 81.35,62.31 81.35,61.51 81.22,61.38 81.22,51.49 80.13,50.4 80.13,44.33 78.32,42.52 78.32,24.71 78.73,24.31 78.73,23.87 78.6,23.74 77.8,23.74 77.67,23.6 77.67,23.41 77.8,23.28 78.6,23.28 78.73,23.15 78.73,22.96 78.6,22.82 77.8,22.82 77.67,22.69 77.67,22.5 77.8,22.36 78.6,22.36 78.73,22.23 78.73,19.25 77.41,17.92 77.41,15.87 78.04,15.24 v1(83.12,15.24)
  BOTTOM w0.147: v1(83.12,15.24) 81.77,13.89 69.71,13.89 69.54,13.72 68.93,13.11 68.93,11.91 64.09,7.06 64.09,6.63 62.58,5.12 62.58,4.37 63.04,3.92 J15.108
HSEC_MII0_RXLINK: length 98.1
  TOP w0.147: U87.26 v1(73.94,62.39)
  L03_SIG1 w0.091: v1(73.94,62.39) 74.27,62.39 75.28,63.4 77.58,63.4 77.98,63.8 77.98,64.02 78.8,64.83 79.21,64.83 81.62,62.42 81.62,61.4 81.49,61.27 81.49,51.37 80.4,50.29 80.4,44.21 78.6,42.41 78.6,41.72 78.71,41.62 79.08,41.62 79.19,41.51 79.19,41.36 79.08,41.25 78.71,41.25 78.6,41.14 78.6,40.99 78.71,40.88 79.08,40.88 79.19,40.78 79.19,40.63 79.08,40.52 78.71,40.52 78.6,40.41 78.6,40.26 78.71,40.15 79.08,40.15 79.19,40.05 79.19,39.89 79.08,39.79 78.71,39.79 78.6,39.68 78.6,39.53 78.71,39.42 79.08,39.42 79.19,39.31 79.19,39.16 79.08,39.06 78.71,39.06 78.6,38.95 78.6,38.8 78.71,38.69 79.08,38.69 79.19,38.58 79.19,38.43 79.08,38.32 78.71,38.32 78.6,38.22 78.6,38.07 78.71,37.96 79.08,37.96 79.19,37.85 79.19,37.7 79.08,37.59 78.71,37.59 78.6,37.49 78.6,37.33 78.71,37.23 79.08,37.23 79.19,37.12 79.19,36.97 79.08,36.86 78.71,36.86 78.6,36.75 78.6,36.6 78.71,36.5 79.08,36.5 79.19,36.39 79.19,36.24 79.08,36.13 78.71,36.13 78.6,36.02 78.6,35.87 78.71,35.76 79.08,35.76 79.19,35.66 79.19,35.51 79.08,35.4 78.71,35.4 78.6,35.29 78.6,35.14 78.71,35.03 79.08,35.03 79.19,34.93 79.19,34.77 79.08,34.67 78.71,34.67 78.6,34.56 78.6,34.41 78.71,34.3 79.08,34.3 79.19,34.19 79.19,34.04 79.08,33.94 78.71,33.94 78.6,33.83 78.6,33.68 78.71,33.57 79.08,33.57 79.19,33.46 79.19,33.31 79.08,33.2 78.71,33.2 78.6,33.1 78.6,32.95 78.71,32.84 79.08,32.84 79.19,32.73 79.19,32.58 79.08,32.47 78.71,32.47 78.6,32.37 78.6,32.21 78.71,32.11 79.08,32.11 79.19,32 79.19,31.85 79.08,31.74 78.71,31.74 78.6,31.63 78.6,31.48 78.71,31.37 79.08,31.37 79.19,31.27 79.19,31.12 79.08,31.01 78.71,31.01 78.6,30.9 78.6,30.75 78.71,30.64 79.08,30.64 79.19,30.54 79.19,30.38 79.08,30.28 78.71,30.28 78.6,30.17 78.6,25.12 79.96,23.75 79.96,19.75 77.85,17.64 77.85,16.07 78.22,15.69 86.65,15.69 88.99,13.35 88.99,6.99 v1(89.4,6.58)
  BOTTOM w0.147: J15.122 88.84,6.02 v1(89.4,6.58)
HSEC_MII0_TXCLK: length 120.7
  TOP w0.147: v1(92.84,6.59) 92.04,5.79 J15.129
  L03_SIG1 w0.091: v1(92.84,6.59) 92.84,6.98 94.21,8.36 94.21,10.96 93.81,11.37 93.81,14.13 92.43,15.51 92.43,17.81 91.61,18.63 91.61,19.25 87.6,23.25 87.6,44.46 88.8,45.66 89.56,45.66 90.03,46.13 90.03,48.78 87.89,50.92 87.89,56.4 87.63,56.66 87.48,56.66 87.34,56.52 87.18,56.52 87.08,56.63 87.08,56.78 87.22,56.92 87.22,57.07 87.11,57.18 86.96,57.18 86.82,57.04 86.67,57.04 86.56,57.15 86.56,57.3 86.7,57.44 86.7,57.59 86.59,57.7 86.44,57.7 86.3,57.56 86.15,57.56 86.04,57.66 86.04,57.81 86.18,57.95 86.18,58.11 86.08,58.21 85.92,58.21 85.78,58.07 85.63,58.07 85.53,58.18 85.53,58.33 85.67,58.47 85.67,58.62 85.26,59.03 85.26,62.6 85.46,62.8 86,62.8 86.75,63.55 86.75,66.02 87.18,66.45 87.18,70.28 87.62,70.71 87.62,74.09 86.75,74.95 86.75,80.78 86.51,81.02 86.51,82.53 85.96,83.09 85.58,83.09 84.23,84.44 82.53,84.44 82.07,84.9 81.91,85.06 81.91,90.36 81.8,90.47 81.05,90.47 80.95,90.58 80.95,90.73 81.05,90.84 81.8,90.84 81.91,90.94 81.91,91.1 81.8,91.2 81.05,91.2 80.95,91.31 80.95,91.46 81.05,91.57 81.8,91.57 81.91,91.68 81.91,91.83 81.8,91.93 81.05,91.93 80.95,92.04 80.95,92.19 81.05,92.3 81.8,92.3 81.91,92.41 81.91,93.2 82.62,93.9 82.62,95.25 83.13,95.76 85.28,95.76 85.46,95.95 85.46,96.16 85.36,96.26 84.83,96.26 84.72,96.37 84.72,96.52 84.83,96.63 85.36,96.63 85.46,96.74 85.46,96.97 85.17,97.27 84.32,97.27 84.09,97.04 v1(84.09,96.55)
  BOTTOM w0.147: U88.40 v1(84.09,96.55)
HSEC_MII0_TXD0: length 120.4
  TOP w0.147: J15.131 v1(92.84,4.56)
  L03_SIG1 w0.091: v1(92.84,4.56) 94.23,5.95 94.23,7.21 95.04,8.02 95.04,11.3 94.64,11.7 94.64,14.74 93.26,16.11 93.26,19.18 92.31,20.14 92.31,20.83 88.42,24.71 88.42,39.72 89.95,41.24 89.95,44.69 90.85,45.6 90.85,50.32 89.67,51.5 89.67,52.8 89.22,53.25 89.22,57.46 88.93,57.75 88.93,57.9 89.21,58.18 89.21,58.34 89.1,58.44 88.95,58.44 88.67,58.16 88.52,58.16 88.41,58.27 88.41,58.42 88.69,58.7 88.69,58.85 88.59,58.96 88.44,58.96 88.15,58.68 88,58.68 87.9,58.78 87.9,58.94 88.18,59.22 88.18,59.37 88.07,59.48 87.92,59.48 87.64,59.19 87.49,59.19 87.38,59.3 87.38,59.45 87.66,59.74 87.66,59.89 87.55,59.99 87.4,59.99 87.12,59.71 86.97,59.71 86.76,59.92 86.76,61.85 87.59,62.68 87.59,65.54 88.72,66.66 88.72,70.54 89.09,70.91 89.09,76.55 88.03,77.61 88.03,81.86 87.36,82.53 87.36,82.85 86.25,83.96 85.94,83.96 85.13,84.77 85.13,92.29 86.38,93.54 87.18,93.54 87.75,92.98 87.75,89.92 87.93,89.74 88.3,89.74 88.51,89.95 88.51,95.24 86.38,97.37 v1(86.38,98.34)
  BOTTOM w0.147: U88.37 v1(86.38,98.34)
HSEC_MII0_TXD1: length 120.7
  L03_SIG1 w0.091: v1(86.38,99.34) 85.86,98.82 85.86,97.44 87.39,95.92 87.39,94.5 86.97,94.08 85.83,94.08 85.72,94.18 85.72,94.53 85.61,94.64 85.46,94.64 85.35,94.53 85.35,94.18 85.25,94.08 85.1,94.08 84.99,94.18 84.99,94.53 84.88,94.64 84.73,94.64 84.62,94.53 84.62,94.18 84.52,94.08 83.66,94.08 82.46,92.87 82.46,85.28 82.76,84.98 84.46,84.98 85.78,83.67 86.15,83.67 87.08,82.74 87.08,82.42 87.76,81.75 87.76,80.64 87.33,80.21 87.33,76.98 88.82,75.5 88.82,71.52 88.44,71.15 88.44,66.85 87.3,65.71 87.3,62.77 85.81,61.28 85.81,59.38 86.28,58.92 86.43,58.92 86.7,59.19 86.85,59.19 86.96,59.08 86.96,58.93 86.69,58.66 86.69,58.51 86.79,58.4 86.94,58.4 87.22,58.67 87.37,58.67 87.48,58.57 87.48,58.41 87.2,58.14 87.2,57.99 87.31,57.88 87.46,57.88 87.73,58.16 87.89,58.16 87.99,58.05 87.99,57.9 87.72,57.62 87.72,57.47 87.83,57.37 87.98,57.37 88.25,57.64 88.4,57.64 88.51,57.53 88.51,57.38 88.24,57.11 88.24,56.96 88.46,56.74 88.46,51.13 90.58,49.01 90.58,45.71 89.67,44.81 89.67,41.35 88.15,39.83 88.15,24.57 92.03,20.69 92.03,20.02 92.99,19.07 92.99,16 94.37,14.62 94.37,11.59 94.76,11.19 94.76,8.13 93.96,7.32 93.96,6.32 93.21,5.58 v1(92.84,5.58)
  BOTTOM w0.147: U88.35 v1(86.38,99.34) ; v1(92.84,5.58) 93.32,5.09 93.32,4.36 92.84,3.87 J15.132
HSEC_MII0_TXD2: length 120.5
  TOP w0.147: v1(91.24,6.59) 91.84,7.2 91.84,7.7 92.33,8.19 92.94,8.19 93.64,7.49 J15.133
  L03_SIG1 w0.091: v1(86.38,100.34) 85.49,99.45 85.49,97.41 85.94,96.96 85.94,95.95 85.46,95.46 83.79,95.46 83.61,95.29 83.61,94.5 82.19,93.08 82.19,85.17 82.65,84.71 84.34,84.71 85.69,83.36 86.07,83.36 86.79,82.64 86.79,81.16 87.06,80.89 87.06,76.87 87.89,76.03 87.89,70.6 87.46,70.17 87.46,66.34 87.03,65.91 87.03,62.89 85.54,61.4 85.54,59.24 88.18,56.61 88.18,51.02 90.3,48.9 90.3,46.02 89.67,45.39 88.91,45.39 87.87,44.35 87.87,23.36 91.29,19.95 91.7,19.95 92.71,18.94 92.71,15.71 94.08,14.33 94.08,11.48 94.49,11.07 94.49,8.24 93.42,7.17 93.42,6.51 92.97,6.06 91.76,6.06 v1(91.24,6.59)
  BOTTOM w0.147: U88.33 v1(86.38,100.34)
HSEC_MII0_TXD3: length 120.7
  L03_SIG1 w0.091: v1(86.38,101.34) 85.87,101.85 85.44,101.85 85.18,101.59 85.18,97.89 84.88,97.59 82.65,97.59 81.63,96.57 81.19,96.57 80.62,96 80.62,94.27 79.61,93.26 79.61,84.76 81.14,83.23 84.48,83.23 85.17,82.54 85.73,82.54 85.97,82.3 85.97,80.8 86.21,80.56 86.21,74.72 87.07,73.86 87.07,70.94 86.64,70.51 86.64,66.73 86.21,66.29 86.21,64.47 85.83,64.09 85.23,64.09 84.72,63.57 84.72,57.25 86.97,55 86.97,51.07 88.85,49.18 88.85,47.57 87.05,45.77 87.05,44.09 84.35,41.39 84.35,33.11 85.33,32.13 85.33,23.69 90.94,18.07 90.94,17.51 91.17,17.28 91.58,17.28 91.88,16.97 91.88,15.28 93.26,13.91 93.26,10.59 v1(92.46,9.78)
  BOTTOM w0.147: J15.134 93.64,4.06 93.96,4.38 93.96,7.75 92.98,8.72 92.98,9.2 92.78,9.4 92.78,9.46 v1(92.46,9.78) ; U88.31 v1(86.38,101.34)
HSEC_MII0_TXEN: length 120.7
  L03_SIG1 w0.091: v1(83.09,96.55) 82.56,96.55 81.55,95.55 81.55,94.57 79.88,92.9 79.88,92.72 79.99,92.62 80.38,92.62 80.49,92.51 80.49,92.36 80.38,92.25 79.99,92.25 79.88,92.14 79.88,91.99 79.99,91.88 80.38,91.88 80.49,91.78 80.49,91.63 80.38,91.52 79.99,91.52 79.88,91.41 79.88,91.26 79.99,91.15 80.38,91.15 80.49,91.05 80.49,90.89 80.38,90.79 79.99,90.79 79.88,90.68 79.88,90.53 79.99,90.42 80.38,90.42 80.49,90.31 80.49,90.16 80.38,90.06 79.99,90.06 79.88,89.95 79.88,89.8 79.99,89.69 80.38,89.69 80.49,89.58 80.49,89.43 80.38,89.32 79.99,89.32 79.88,89.22 79.88,89.07 79.99,88.96 80.38,88.96 80.49,88.85 80.49,88.7 80.38,88.59 79.99,88.59 79.88,88.49 79.88,87.43 79.99,87.33 80.38,87.33 80.49,87.22 80.49,87.07 80.38,86.96 79.99,86.96 79.88,86.85 79.88,86.7 79.99,86.59 80.38,86.59 80.49,86.49 80.49,86.34 80.38,86.23 79.99,86.23 79.88,86.12 79.88,85.97 79.99,85.86 80.38,85.86 80.49,85.76 80.49,85.6 80.38,85.5 79.99,85.5 79.88,85.39 79.88,84.88 80.66,84.1 84.18,84.1 85.46,82.81 85.84,82.81 86.24,82.42 86.24,80.91 86.48,80.67 86.48,74.84 87.34,73.97 87.34,70.83 86.91,70.4 86.91,66.57 86.48,66.14 86.48,63.66 85.89,63.07 85.35,63.07 84.99,62.71 84.99,57.36 85.52,56.83 85.67,56.83 85.76,56.92 85.91,56.92 86.02,56.81 86.02,56.66 85.93,56.57 85.93,56.42 86.04,56.31 86.19,56.31 86.28,56.4 86.43,56.4 86.54,56.29 86.54,56.14 86.45,56.05 86.45,55.9 86.56,55.8 86.71,55.8 86.79,55.88 86.95,55.88 87.05,55.78 87.05,55.62 86.97,55.54 86.97,55.39 87.24,55.11 87.24,51.18 89.13,49.29 89.13,47.46 87.33,45.66 87.33,43.94 85.6,42.21 85.6,24.78 91.33,19.05 91.33,18.52 92.16,17.69 92.16,15.39 93.53,14.02 93.53,11.25 93.94,10.85 93.94,8.47 93.34,7.87 93.1,7.87 v1(92.84,7.61)
  BOTTOM w0.147: U88.42 v1(83.09,96.55) ; v1(92.84,7.61) 92.04,6.81 J15.130
HSEC_MII1_COL: length 102
  L03_SIG1 w0.091: v1(96.04,6.59) 96.52,7.08 96.52,11.95 95.87,12.6 95.87,18.95 96.1,19.19 96.1,20.32 95.66,20.77 95.12,20.77 89.52,26.37 89.52,39.26 91.04,40.78 91.04,44.24 92.65,45.84 92.65,47.47 92.26,47.87 92.26,53.05 91.14,54.16 91.14,59.71 92.69,61.25 92.69,65.22 91.87,66.04 91.87,70.95 91.25,71.57 91.25,75.94 89.13,78.06 89.13,80.99 89.61,81.47 89.61,83.93 89.21,84.33 88.19,84.33 87.92,84.61 86.09,84.61 85.68,85.02 85.68,91.15 v1(86.38,91.85)
  BOTTOM w0.147: J15.138 95.24,5.79 v1(96.04,6.59) ; U89.24 v1(86.38,91.85)
HSEC_MII1_CRS(RES0_PWMOUT0): length 178.9
  TOP w0.147: v1(47.22,14.32) 47.87,13.67 U73.10 ; v1(96.04,7.61) 95.5,7.07 95.5,4.45 96.04,3.91 J15.139
  L03_SIG1 w0.091: v1(96.04,7.61) 96.04,12.04 95.59,12.49 95.59,18.25 95.01,18.82 95.01,20.48 89.25,26.25 89.25,39.38 90.77,40.9 90.77,44.35 91.67,45.26 91.67,52.2 90.19,53.69 90.19,59.14 92.41,61.36 92.41,65.11 91.6,65.92 91.6,70.84 90.98,71.46 90.98,75.82 88.85,77.95 88.85,81.1 89.34,81.59 89.34,82.92 89.02,83.23 88.39,83.23 87.3,84.33 85.97,84.33 85.4,84.9 85.4,91.87 v1(86.38,92.85)
  L08_SIG2 w0.091: v1(47.22,14.32) 46.8,13.9 46.8,11.1 44.63,8.93 44.63,4.21 45.9,2.93 63.62,2.93 65.41,4.72 65.41,7.38 66.49,8.47 67.54,8.47 68.69,9.62 68.69,12.16 70.16,13.63 91.65,13.63 96.04,9.25 v1(96.04,7.61)
  BOTTOM w0.147: U89.22 v1(86.38,92.85)
HSEC_MII1_RXCLK: length 106.4
  TOP w0.147: J15.141 96.84,7.69 97.31,8.17 97.75,8.17 v1(99.32,6.59)
  L03_SIG1 w0.091: v1(86.38,89.85) 86.92,89.3 90,89.3 91.07,88.23 92.53,88.23 93.83,86.94 93.83,85.31 94.6,84.54 94.6,83.57 93.74,82.72 93.74,77.92 93.11,77.29 93.11,74.31 93.82,73.6 93.82,71.4 94.23,70.99 94.23,66.07 95.04,65.26 95.04,60.43 95.76,59.71 95.76,50.62 94.9,49.76 94.9,42.05 92.16,39.3 92.16,31.32 96.91,26.57 96.91,22.58 99.16,20.33 99.16,16.68 97.96,15.48 97.96,14.77 98.72,14.02 98.72,9.97 99.82,8.87 99.82,7.08 v1(99.32,6.59)
  BOTTOM w0.147: U89.28 v1(86.38,89.85)
HSEC_MII1_RXD0: length 106.3
  TOP w0.147: J15.143 v1(97.64,4.56)
  L03_SIG1 w0.091: v1(87.8,82.71) 88.3,82.21 88.3,77.72 90.39,75.64 90.39,72.53 89.62,71.76 89.62,66.93 88.93,66.25 88.93,62.34 89.16,62.12 90.7,62.12 91.05,61.77 91.05,60.77 89.64,59.36 89.64,53.46 91.13,51.98 91.13,45.48 90.22,44.58 90.22,41.13 88.7,39.6 88.7,25.38 93.65,20.42 93.65,16.26 95.04,14.87 95.04,12.26 95.31,11.99 95.31,7.9 94.91,7.51 94.91,6.18 93.41,4.68 93.41,3.31 93.77,2.95 97.6,2.95 97.73,3.08 97.73,3.61 97.87,3.74 98.06,3.74 98.19,3.61 98.19,3.08 98.33,2.95 98.74,2.95 98.97,3.18 98.97,4.05 98.45,4.56 v1(97.64,4.56)
  BOTTOM w0.147: U89.42 83.09,83.32 83.7,82.71 v1(87.8,82.71)
HSEC_MII1_RXD1: length 106.2
  L03_SIG1 w0.091: v1(97.64,5.58) 97.15,5.08 97.15,3.73 96.7,3.29 96.15,3.29 96.02,3.42 96.02,3.89 95.88,4.02 95.7,4.02 95.56,3.89 95.56,3.42 95.43,3.29 95.24,3.29 95.1,3.42 95.1,3.89 94.97,4.02 94.78,4.02 94.65,3.89 94.65,3.42 94.51,3.29 94.02,3.29 93.75,3.56 93.75,4.55 95.28,6.08 95.28,7.49 95.59,7.79 95.59,12.11 95.31,12.38 95.31,14.98 93.95,16.35 93.95,20.54 88.97,25.52 88.97,39.49 90.49,41.01 90.49,44.47 91.4,45.37 91.4,52.09 89.91,53.58 89.91,59.25 91.95,61.29 91.95,62.16 91.58,62.54 89.7,62.54 89.3,62.95 89.3,66 89.95,66.65 89.95,71.62 90.7,72.37 90.7,75.71 88.58,77.83 88.58,82.36 88.27,82.67 88.27,82.92 87.46,83.73 v1(87.09,83.73)
  BOTTOM w0.147: v1(87.09,83.73) 86.77,83.41 84.4,83.41 84.09,83.71 U89.40 ; v1(97.64,5.58) 97.1,5.04 97.1,4.45 97.64,3.92 J15.144
HSEC_MII1_RXD2: length 106.2
  TOP w0.147: v1(97.64,7.61) 98.18,7.06 98.18,4.25 98.44,4 J15.145
  L03_SIG1 w0.091: v1(86.38,85.35) 87.72,85.35 88.73,86.36 89.27,86.36 89.53,86.1 89.53,85.39 90.85,84.07 90.85,78.85 91.86,77.84 91.86,71.74 92.42,71.18 92.42,66.26 93.23,65.45 93.23,61.01 92.7,60.47 92.7,57.49 93.64,56.55 93.64,45.34 92.97,44.67 92.97,41.69 90.07,38.79 90.07,37.34 90.21,37.21 90.5,37.21 90.63,37.07 90.63,36.88 90.5,36.75 90.21,36.75 90.07,36.62 90.07,36.43 90.21,36.29 90.5,36.29 90.63,36.16 90.63,35.97 90.5,35.84 90.21,35.84 90.07,35.7 90.07,34.62 90.21,34.49 90.74,34.49 90.88,34.36 90.88,34.17 90.74,34.03 90.21,34.03 90.07,33.9 90.07,33.71 90.21,33.57 90.74,33.57 90.88,33.44 90.88,33.25 90.74,33.12 90.21,33.12 90.07,32.98 90.07,32.79 90.21,32.66 90.74,32.66 90.88,32.53 90.88,32.34 90.74,32.2 90.21,32.2 90.07,32.07 90.07,31.88 90.21,31.75 90.74,31.75 90.88,31.61 90.88,31.42 90.74,31.29 90.21,31.29 90.07,31.15 90.07,30.97 90.21,30.83 90.74,30.83 90.88,30.7 90.88,30.51 90.74,30.37 90.21,30.37 90.07,30.24 90.07,30.05 90.21,29.92 90.74,29.92 90.88,29.78 90.88,29.59 90.74,29.46 90.21,29.46 90.07,29.33 90.07,29.14 90.21,29 90.74,29 90.88,28.87 90.88,28.68 90.74,28.55 90.21,28.55 90.07,28.41 90.07,27.47 96.72,20.83 96.72,18.95 96.43,18.66 96.43,12.81 97.07,12.17 97.07,8.17 v1(97.64,7.61)
  BOTTOM w0.147: U89.37 v1(86.38,85.35)
HSEC_MII1_RXD3: length 106.2
  L03_SIG1 w0.091: v1(97.64,6.59) 98.18,7.13 98.18,8.04 97.34,8.88 97.34,12.31 96.72,12.94 96.72,15.85 97.58,16.71 97.58,20.46 95.19,22.84 95.19,24.7 92.42,27.48 92.23,27.48 92.1,27.34 92.1,27.15 94.63,24.62 94.63,24.46 94.47,24.3 94.3,24.3 91.29,27.31 91.29,39.6 93.25,41.55 93.25,44.56 93.92,45.23 93.92,56.67 92.98,57.6 92.98,60.36 94.2,61.59 94.2,64.87 92.69,66.38 92.69,71.29 92.13,71.85 92.13,77.95 91.85,78.24 91.85,84.05 91.37,84.53 90.82,84.53 89.9,85.45 89.9,86.72 89.33,87.29 88.7,87.29 87.76,86.35 v1(86.38,86.35)
  BOTTOM w0.147: v1(97.64,6.59) 98.44,5.79 J15.146 ; U89.35 v1(86.38,86.35)
HSEC_MII1_RXDV: length 106.1
  L03_SIG1 w0.091: v1(96.04,4.56) 96.5,5.03 96.5,5.19 97.37,6.06 97.91,6.06 98.5,6.65 98.5,8.88 98.17,9.22 98.17,12.91 97.05,14.04 97.05,15.62 98.56,17.13 98.56,19.97 95.61,22.92 95.61,24.95 94.79,25.78 94.79,25.97 95.32,26.51 95.32,26.7 95.19,26.83 95,26.83 94.46,26.3 94.27,26.3 94.14,26.43 94.14,26.62 94.67,27.15 94.67,27.34 94.54,27.48 94.35,27.48 93.82,26.94 93.63,26.94 92.2,28.37 92.2,28.56 92.73,29.09 92.73,29.28 92.6,29.42 92.41,29.42 91.88,28.88 91.69,28.88 91.6,28.97 91.6,39.52 93.52,41.44 93.52,44.45 94.19,45.12 94.19,56.78 93.26,57.72 93.26,60.25 94.48,61.48 94.48,65.02 93.01,66.49 93.01,73.59 92.41,74.19 92.41,82.67 92.88,83.14 92.88,85.52 92.54,85.86 90.67,85.86 90.26,86.27 90.26,86.87 89.33,87.81 86.84,87.81 v1(86.38,87.35)
  BOTTOM w0.147: U89.33 v1(86.38,87.35) ; J15.142 96.84,4.06 96.34,4.56 v1(96.04,4.56)
HSEC_MII1_RXER: length 106
  TOP w0.147: v1(99.32,7.61) 98.22,8.71 96.27,8.71 95.03,7.47 95.03,4.23 95.24,4.02 J15.137
  L03_SIG1 w0.091: v1(99.32,7.61) 99.32,8.97 98.44,9.86 98.44,13.9 97.69,14.66 97.69,15.66 98.88,16.86 98.88,20.13 95.9,23.11 95.9,27.07 91.88,31.09 91.88,39.41 93.8,41.33 93.8,44.33 94.47,45.01 94.47,56.96 93.56,57.87 93.56,60.17 94.77,61.38 94.77,65.15 93.96,65.96 93.96,70.87 93.54,71.29 93.54,73.49 92.68,74.35 92.68,77.25 93.47,78.04 93.47,82.9 93.83,83.27 93.83,83.83 93.52,84.14 93.52,86.52 92.83,87.21 90.48,87.21 89.41,88.29 88.38,88.29 87.77,88.89 86.93,88.89 v1(86.38,88.35)
  BOTTOM w0.147: U89.31 v1(86.38,88.35)
HSEC_MII1_RXLINK: length 106.2
  L03_SIG1 w0.091: v1(96.04,5.58) 96.8,6.34 96.8,12.06 96.15,12.7 96.15,18.81 96.44,19.1 96.44,20.37 89.79,27.02 89.79,39.15 90.1,39.45 91.32,40.67 91.32,44.04 92.96,45.68 92.96,47.71 92.53,48.14 92.53,48.57 92.67,48.7 92.91,48.7 93.05,48.83 93.05,49.02 92.91,49.16 92.67,49.16 92.53,49.29 92.53,49.48 92.67,49.62 92.91,49.62 93.05,49.75 93.05,49.94 92.91,50.07 92.67,50.07 92.53,50.21 92.53,50.4 92.67,50.53 92.91,50.53 93.05,50.66 93.05,50.85 92.91,50.99 92.67,50.99 92.53,51.12 92.53,51.31 92.67,51.44 92.91,51.44 93.05,51.58 93.05,51.77 92.91,51.9 92.67,51.9 92.53,52.04 92.53,55.69 91.68,56.54 91.68,57.08 91.82,57.21 92.1,57.21 92.24,57.35 92.24,57.54 92.1,57.67 91.82,57.67 91.68,57.81 91.68,57.99 91.82,58.13 92.1,58.13 92.24,58.26 92.24,58.45 92.1,58.59 91.82,58.59 91.68,58.72 91.68,58.91 91.82,59.04 92.1,59.04 92.24,59.18 92.24,59.37 92.1,59.5 91.82,59.5 91.68,59.63 91.68,59.86 92.96,61.14 92.96,65.33 92.14,66.15 92.14,71.07 91.58,71.63 91.58,77.72 89.89,79.42 89.89,84.64 89.2,85.33 88.29,85.33 87.84,84.88 86.2,84.88 85.95,85.13 85.95,90.42 v1(86.38,90.85)
  BOTTOM w0.147: v1(96.04,5.58) 95.58,5.12 95.58,4.37 96.04,3.92 J15.140 ; U89.26 v1(86.38,90.85)
HSEC_MII1_TXCLK: length 124.2
  TOP w0.147: v1(99.24,5.58) 99.76,5.05 99.76,4.41 99.24,3.89 J15.147
  L03_SIG1 w0.091: v1(83.09,107.12) 84.1,106.11 85.84,106.11 86.01,106.28 86.61,106.28 87.09,105.8 87.09,105.17 88,104.26 89.24,104.26 89.56,103.95 89.56,103.44 89.94,103.06 89.94,96.55 90.5,95.99 93.16,95.99 95.96,93.18 95.96,91.28 96.95,90.29 96.95,79.79 95.89,78.73 95.89,71.18 96.43,70.64 96.43,62.3 97.26,61.47 97.26,49.37 97.11,49.22 97.11,48.04 96.28,47.21 96.28,37.23 95.5,36.46 95.5,31.33 99.82,27.01 99.82,25.29 100.77,24.34 100.77,15.3 101.17,14.89 101.17,10.11 101.57,9.71 101.57,4.67 100.99,4.09 100.53,4.09 99.5,5.12 99.5,5.31 v1(99.24,5.58)
  BOTTOM w0.147: U88.18 v1(83.09,107.12)
HSEC_MII1_TXD0: length 124.1
  TOP w0.147: v1(100.84,5.58) 100.3,5.04 100.3,4.26 100.04,4 J15.149
  L03_SIG1 w0.091: v1(86.38,102.84) 86.75,102.84 87.82,101.76 87.82,101.2 87.59,100.97 87.59,97.1 89.53,95.16 92.39,95.16 93.16,94.4 93.16,89.36 94.51,88.01 94.51,85.55 95.16,84.9 95.16,83.34 94.36,82.54 94.36,71.63 94.78,71.21 94.78,66.3 95.59,65.49 95.59,60.76 96.36,59.99 96.36,50.39 95.45,49.49 95.45,40.16 93.57,38.28 93.57,35.13 93.7,34.99 94.1,34.99 94.23,34.86 94.23,34.67 94.1,34.54 93.7,34.54 93.57,34.4 93.57,34.21 93.7,34.08 94.1,34.08 94.23,33.95 94.23,33.76 94.1,33.62 93.7,33.62 93.57,33.49 93.57,33.3 93.7,33.17 94.1,33.17 94.23,33.03 94.23,32.84 94.1,32.71 93.7,32.71 93.57,32.57 93.57,32.03 93.95,31.65 93.95,31.46 93.55,31.07 93.55,30.88 93.69,30.75 93.88,30.75 94.27,31.14 94.46,31.14 94.59,31.01 94.59,30.82 94.2,30.43 94.2,30.24 94.34,30.1 94.52,30.1 94.92,30.49 95.11,30.49 95.24,30.36 95.24,30.17 94.85,29.78 94.85,29.59 94.98,29.46 95.17,29.46 95.56,29.85 95.75,29.85 95.89,29.71 95.89,29.52 95.49,29.13 95.49,28.94 95.63,28.81 95.82,28.81 96.21,29.2 96.4,29.2 96.53,29.07 96.53,28.88 96.14,28.49 96.14,28.3 96.27,28.16 96.46,28.16 96.86,28.55 97.05,28.55 97.18,28.42 97.18,28.23 96.79,27.84 96.79,27.65 96.92,27.52 97.11,27.52 97.5,27.91 97.69,27.91 97.98,27.62 97.98,25.46 99.82,23.62 99.82,15.39 99.27,14.84 99.27,10.2 100.37,9.1 100.37,6.04 v1(100.84,5.58)
  BOTTOM w0.147: U88.28 v1(86.38,102.84)
HSEC_MII1_TXD1: length 124.1
  L03_SIG1 w0.091: v1(86.38,103.84) 88.61,101.6 88.61,96.47 89.65,95.44 92.66,95.44 93.43,94.66 93.43,89.65 93.69,89.4 93.88,89.4 94.51,90.03 94.7,90.03 94.84,89.9 94.84,89.71 94.2,89.07 94.2,88.88 94.34,88.75 94.53,88.75 95.16,89.38 95.35,89.38 95.48,89.25 95.48,89.06 94.85,88.43 94.85,88.24 94.98,88.1 95.17,88.1 95.81,88.74 96,88.74 96.13,88.6 96.13,88.41 95.5,87.78 95.5,87.59 96.34,86.75 96.34,86.27 96.2,86.14 95.87,86.14 95.73,86 95.73,85.81 95.87,85.68 96.2,85.68 96.34,85.55 96.34,85.36 96.2,85.22 95.87,85.22 95.73,85.09 95.73,84.9 95.87,84.77 96.2,84.77 96.34,84.63 96.34,84.44 96.2,84.31 95.87,84.31 95.73,84.17 95.73,83.98 95.87,83.85 96.2,83.85 96.34,83.72 96.34,83.53 96.2,83.39 95.87,83.39 95.73,83.26 95.73,83.07 95.87,82.94 96.2,82.94 96.34,82.8 96.34,81.72 94.64,80.03 94.64,71.74 95.05,71.33 95.05,66.42 95.88,65.59 95.88,60.87 96.63,60.12 96.63,50.25 95.73,49.34 95.73,38.99 93.89,37.16 93.89,35.82 94.85,34.86 94.85,31.2 98.3,27.76 98.3,25.65 100.12,23.83 100.12,15.19 99.55,14.62 99.55,10.31 100.84,9.02 v1(100.84,7.61)
  BOTTOM w0.147: v1(100.84,7.61) 100.28,7.05 100.28,4.32 100.04,4.07 J15.150 ; U88.26 v1(86.38,103.84)
HSEC_MII1_TXD2: length 124.3
  TOP w0.147: J15.151 100.84,3.88 101.43,4.47 101.43,6 v1(100.84,6.59)
  L03_SIG1 w0.091: v1(100.84,6.59) 101.3,7.06 101.3,9.25 100.78,9.77 100.78,14.84 100.44,15.18 100.44,23.9 98.75,25.58 98.75,27.69 95.19,31.25 95.19,35.02 94.42,35.8 94.42,36.42 95.12,37.12 95.12,37.55 96,38.43 96,49.17 96.91,50.08 96.91,60.26 96.15,61.01 96.15,65.7 95.33,66.53 95.33,73.3 95.61,73.59 95.61,78.84 96.68,79.9 96.68,89.25 95.57,90.35 95.57,93.04 95.31,93.3 94.84,93.3 94.62,93.09 94.62,91.09 94.37,90.83 93.95,90.83 93.71,91.08 93.71,94.9 92.89,95.71 90.38,95.71 89.67,96.43 89.67,96.7 89.53,96.84 89.23,96.84 89.1,96.97 89.1,97.16 89.23,97.29 89.53,97.29 89.67,97.43 89.67,97.62 89.53,97.75 89.23,97.75 89.1,97.88 89.1,98.07 89.23,98.21 89.53,98.21 89.67,98.34 89.67,98.53 89.53,98.66 89.23,98.66 89.1,98.8 89.1,98.99 89.23,99.12 89.53,99.12 89.67,99.26 89.67,99.44 89.53,99.58 89.23,99.58 89.1,99.71 89.1,99.9 89.23,100.04 89.53,100.04 89.67,100.17 89.67,102.84 89.19,103.31 87.9,103.31 v1(86.38,104.84)
  BOTTOM w0.147: U88.24 v1(86.38,104.84)
HSEC_MII1_TXD3: length 123.9
  L03_SIG1 w0.091: v1(86.38,105.84) 82.32,105.84 82.09,105.61 82.09,102.79 82.62,102.27 86.17,102.27 86.83,101.6 86.83,97.48 89.42,94.89 92.02,94.89 92.88,94.03 92.88,89.18 94.19,87.87 94.19,85.42 94.89,84.71 94.89,83.46 94.09,82.66 94.09,71.51 94.5,71.1 94.5,66.19 95.32,65.38 95.32,60.62 96.09,59.85 96.09,50.51 95.18,49.6 95.18,40.31 92.43,37.57 92.43,31.45 97.21,26.67 97.21,22.71 99.48,20.44 99.48,15.44 99,14.95 99,10.09 100.1,8.98 100.1,5.3 v1(100.84,4.56)
  BOTTOM w0.147: J15.152 v1(100.84,4.56) ; U88.22 v1(86.38,105.84)
HSEC_MII1_TXEN: length 124
  L03_SIG1 w0.091: v1(99.24,4.56) 99.98,3.82 101.49,3.82 101.85,4.18 101.85,9.82 101.44,10.23 101.44,15.12 101.04,15.52 101.04,26.18 95.83,31.39 95.83,34.14 96.55,34.86 96.55,47.09 98.22,48.76 98.22,49.24 97.65,49.8 97.65,61.6 96.7,62.55 96.7,79.15 97.7,80.15 97.7,89.93 97.04,90.59 97.04,95.17 95.06,97.15 90.94,97.15 90.21,97.88 90.21,103.17 89.85,103.53 89.85,104.1 89.4,104.56 88.14,104.56 87.49,105.21 87.49,105.84 86.76,106.57 85.91,106.57 85.73,106.38 84.3,106.38 84.09,106.59 v1(84.09,107.12)
  BOTTOM w0.147: v1(99.24,4.56) J15.148 ; U88.20 v1(84.09,107.12)
HSEC_MMC0_CLK: length 104.7
  TOP w0.147: J15.163 105.64,3.79 106.21,4.36 106.21,6.02 v1(105.64,6.59)
  L08_SIG2 w0.091: v1(51.14,52.98) 52.99,54.83 65.19,54.83 66.35,53.66 67.35,53.66 68.11,52.91 70.19,52.91 71.22,51.88 75.7,51.88 78.49,49.09 78.49,40.65 80.09,39.04 80.09,33.19 81.06,32.22 81.06,30.93 84.88,27.1 84.88,25.92 85.01,25.79 85.41,25.79 85.55,25.66 85.55,25.47 85.41,25.33 85.01,25.33 84.88,25.2 84.88,25.01 85.01,24.87 85.41,24.87 85.55,24.74 85.55,24.55 85.41,24.42 85.01,24.42 84.88,24.28 84.88,24.09 85.01,23.96 85.41,23.96 85.55,23.83 85.55,23.64 85.41,23.5 85.01,23.5 84.88,23.37 84.88,23.18 85.01,23.05 85.41,23.05 85.55,22.91 85.55,22.72 85.41,22.59 85.01,22.59 84.88,22.45 84.88,21.89 85.19,21.57 85.38,21.57 85.73,21.92 85.92,21.92 86.05,21.79 86.05,21.6 85.71,21.25 85.71,21.06 85.84,20.93 86.03,20.93 86.38,21.27 86.57,21.27 86.7,21.14 86.7,20.95 86.35,20.6 86.35,20.41 86.49,20.28 86.68,20.28 87.02,20.63 87.21,20.63 87.35,20.49 87.35,20.3 87,19.96 87,19.77 87.13,19.63 87.32,19.63 87.67,19.98 87.86,19.98 87.99,19.85 87.99,19.66 87.65,19.31 87.65,19.12 87.78,18.99 87.97,18.99 88.32,19.33 88.51,19.33 88.64,19.2 88.64,19.01 88.29,18.66 88.29,18.47 88.43,18.34 88.62,18.34 88.96,18.69 89.15,18.69 89.29,18.55 89.29,18.36 88.94,18.02 88.94,17.83 89.46,17.31 91.77,17.31 100.16,8.92 101.52,8.92 103.12,7.32 104.91,7.32 v1(105.64,6.59)
  BOTTOM w0.147: RA3.4 50.49,52.6 50.86,52.98 v1(51.14,52.98)
HSEC_MMC0_CMD: length 105
  L08_SIG2 w0.091: v1(105.64,5.58) 106.25,4.96 106.25,4.67 106.79,4.13 107.49,4.13 107.96,4.61 107.96,7.91 107.41,8.47 103.59,8.47 103.04,9.01 103.04,9.28 100.51,11.81 99.92,11.81 97.99,13.74 97.07,13.74 93.37,17.44 93.37,19.31 92.15,20.52 92.15,21.62 84.22,29.55 84.22,31.85 83.54,32.54 83.54,40.15 81.71,41.98 81.71,44.83 79.58,46.96 79.58,50.83 77.45,52.97 71.6,52.97 70.89,53.68 68.43,53.68 67.67,54.44 66.67,54.44 65.51,55.6 49.19,55.6 v1(46.57,52.98)
  BOTTOM w0.147: v1(46.57,52.98) 46.57,52.94 46.3,52.66 RA5.3 ; v1(105.64,5.58) 105.18,5.12 105.18,4.37 105.64,3.92 J15.164
HSEC_MMC0_D0: length 105.1
  TOP w0.147: J15.165 106.44,4.03 106.66,4.26 106.66,6.02 v1(107.24,6.59)
  L08_SIG2 w0.091: v1(107.24,6.59) 106.18,7.64 103.25,7.64 101.7,9.19 100.28,9.19 92.52,16.95 92.52,17.77 91.82,18.47 90.22,18.47 86.14,22.55 86.14,26.26 82.24,30.16 82.24,31.78 82.11,31.91 81.73,31.91 81.59,32.04 81.59,32.23 81.73,32.37 82.11,32.37 82.24,32.5 82.24,32.69 82.11,32.82 81.73,32.82 81.59,32.96 81.59,33.15 81.73,33.28 82.11,33.28 82.24,33.42 82.24,33.61 82.11,33.74 81.73,33.74 81.59,33.87 81.59,34.06 81.73,34.2 82.11,34.2 82.24,34.33 82.24,34.52 82.11,34.65 81.73,34.65 81.59,34.79 81.59,34.98 81.73,35.11 82.11,35.11 82.24,35.24 82.24,35.43 82.11,35.57 81.73,35.57 81.59,35.7 81.59,35.89 81.73,36.02 82.11,36.02 82.24,36.16 82.24,36.35 82.11,36.48 81.73,36.48 81.59,36.62 81.59,36.81 81.73,36.94 82.11,36.94 82.24,37.07 82.24,37.57 80.11,39.7 80.11,40.95 79.98,41.08 79.6,41.08 79.47,41.21 79.47,41.4 79.6,41.54 79.98,41.54 80.11,41.67 80.11,41.86 79.98,41.99 79.6,41.99 79.47,42.13 79.47,42.32 79.6,42.45 79.98,42.45 80.11,42.59 80.11,42.77 79.98,42.91 79.6,42.91 79.47,43.04 79.47,43.23 79.6,43.37 79.98,43.37 80.11,43.5 80.11,43.69 79.98,43.82 79.6,43.82 79.47,43.96 79.47,44.15 79.6,44.28 79.98,44.28 80.11,44.41 80.11,44.93 78.76,46.29 78.76,49.13 75.78,52.11 71.33,52.11 70.34,53.1 68.19,53.1 67.43,53.86 66.43,53.86 65.27,55.02 52.17,55.02 v1(50.12,52.98)
  BOTTOM w0.147: RA3.3 49.85,52.66 50.12,52.94 v1(50.12,52.98)
